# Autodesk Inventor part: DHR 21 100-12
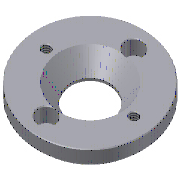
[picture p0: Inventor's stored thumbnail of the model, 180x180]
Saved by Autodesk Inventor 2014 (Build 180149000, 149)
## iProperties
IsCustomPart: 1
Created: 2009-11
Part Number: DHR 21 100-12
Material: DIN 1.1730
Description: Locating Ring
Document SubType Name: Modeling
Designer: gaom
Standard Revision: 1
Manufacturer: DME
Language: en-US
Size Designation: DHR 21 100-12
Categories: <MemberInstance><Categories><Category DisplayName="Mold" InternalName="349578f2-f4d4-4954-8c09-8e99297a61c0" Mnemonic="MOLD"><Category DisplayName="Locatings" I
Density: 7.82 g/cm^3
Appearance: Default
Author: gaom
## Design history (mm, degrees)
sketch "Sketch1"
  geometry: L1 (0, -6.4)-(0, 10.4) reference; L2 (28.5, 8)-(18, -2.5); L3 (18, -2.5)-(18, -4); L4 (18, -4)-(45, -4); L5 (45, -4)-(45, 0); L6 (45, 0)-(50, 0); L7 (50, 0)-(50, 8); L8 (50, 8)-(28.5, 8); 1 further point
  constraints: 14 end point, 3 horizontal, 3 vertical, 1 point on line
  dimensions: "d0" = 45 deg angle of L1 L2; "d1" = 100 diameter of L7 L1 (= D); "d3" = 12 distance between parallel lines of L4 L8 (= H_); "d4" = 4 distance between parallel lines of L4 L6 (= h__); "d5" = 90 diameter of L5 L1 (= d2); "d6" = 36 diameter of L3 L1 (= d_); "d7" = 57 diameter of L2.start L1
revolve "Revolution1" sketch "Sketch1" stored, may be unused: angle "d8" = 90 deg
sketch "Sketch2"
  geometry: 3 further points
  constraints: 2 vertical alignment
  dimensions: "d39" = 35.5 distance of point (0, 0) point (0, 35.5); "d40" = 35.5 distance of point (0, -35.5) point (0, 0)
hole "Hole1" sketch "Sketch2" diameter "d10" = 8.5; stored, may be unused: countersink angle "d14" = 90 deg, drill point angle "d16" = 0 deg; dims "d11" = 6, "d12" = 15, "d13" = 9, "d15" = 12 (= H_)
sketch "Sketch3"
  geometry: 3 further points
  constraints: 2 horizontal alignment
  dimensions: "d48" = 35.5 distance of point (0, 0) point (-35.5, 0); "d49" = 35.5 distance of point (35.5, 0) point (0, 0)
hole "Hole3" sketch "Sketch3" diameter "d18" = 6.647; stored, may be unused: countersink angle "d22" = 90 deg, drill point angle "d24" = 0 deg; dims "d19" = 6, "d20" = 15, "d21" = 9, "d23" = 12 (= H_)
hole "Hole2" sketch "Sketch2" diameter "d41" = 8.5; stored, may be unused: countersink angle "d45" = 90 deg, drill point angle "d47" = 0 deg; dims "d42" = 6, "d43" = 15, "d44" = 9, "d46" = 12 (= H_)
hole "Hole4" sketch "Sketch3" diameter "d50" = 6.647; stored, may be unused: countersink angle "d54" = 90 deg, drill point angle "d56" = 0 deg; dims "d51" = 6, "d52" = 15, "d53" = 9, "d55" = 12 (= H_)
chamfer "Chamfer1" distance "d25" = 0.5; stored, may be unused: second distance "d26" = 2, angle "d27" = 45 deg
sketch "Sketch4"
  geometry: L1 (0, -6.4)-(0, 10.4) reference; L2 (0, 8)-(50, 8); L3 (50, 8)-(50, 0); L4 (50, 0)-(45, 0); L5 (45, 0)-(45, -4); L6 (45, -4)-(0, -4); L7 (0, -4)-(0, 8); 1 further point
  constraints: 12 end point, 3 horizontal, 3 point on line, 3 vertical
  dimensions: "d31" = 100 diameter of L3 L1 (= D_CS); "d32" = 90 diameter of L5 L1 (= d2_CS); "d33" = 12 distance between parallel lines of L6 L2 (= H_CS); "d34" = 4 distance between parallel lines of L6 L4 (= h2_CS)
feature "RevolutionSrf1" sketch "Sketch4" dims angle "d35" = 90 deg
body "Solid1"
body "Srf1"
other parameters: "D" = 100 [user parameter; used in 1 equation term], "H_" = 12 [user parameter; used in 5 equation terms], "d_" = 36 [user parameter; used in 1 equation term], "h__" = 4 [user parameter; used in 1 equation term], "d2" = 90 [user parameter; used in 1 equation term], "D_CS" = 100 [user parameter; used in 1 equation term], "H_CS" = 12 [user parameter; used in 1 equation term], "d2_CS" = 90 [user parameter; used in 1 equation term], "h2_CS" = 4 [user parameter; used in 1 equation term], "d36" = 0, "d37" = 0, "d38" = 0
